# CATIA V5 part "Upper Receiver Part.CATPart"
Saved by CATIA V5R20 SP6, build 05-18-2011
Part number: Upper Receiver Part
Bounding box of the stored display mesh (mm): x -116 to 116, y -29.997 to 29.997, z -32.891 to 0
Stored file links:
  E:\LCS\20170920\#01 CATIA Lecture Materials\#55 GSD18\#01 CATPart\Upper Receiver Part.CATPart
  E:\LCS\20170920\#01 CATIA Lecture Materials\#55 GSD18\#01 CATPart\Receiver Assembly.CATProduct
  E:\LCS\20170920\#01 CATIA Lecture Materials\#55 GSD18\#01 CATPart\Skeleton.CATPart
  E:\LCS\20170920\#01 CATIA Lecture Materials\#55 GSD18\#01 CATPart\Lower Receiver Part.CATPart
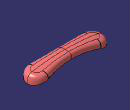
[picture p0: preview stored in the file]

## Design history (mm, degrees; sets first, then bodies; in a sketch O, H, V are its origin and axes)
Set1
  DatumCurve1 "Upper Boundary Curve": linked copy from another document
  DatumCurve2 "Middle Boundary Curve": linked copy from another document
  DatumCurve3 "Upper Guide Curve": linked copy from another document
  DatumCurve4 "Lower Guide Curve": linked copy from another document
Set2 "Surface Data"
  Set3 "Cavity Body"
    CurvePar1 "Center Curve": Offset DatumCurve1, Offset2 0, Offset1 100
    Sweep1 "Top Surface": type Circle, Guide CurvePar1, Reference DatumCurve1, Radius 20, Angle1 0, Angle2 45
    Sweep2 "Parting Surface": type Segment, GuideCrv DatumCurve2, Length1 80, Length2 0, Angle 0, DraftDirection zx-plane
    Project1 "Side Surface Guide Curve 01": ToProject DatumCurve3, Support Sweep1, Direction xy-plane
    Sweep3 "Side Surface": type Conic, Guide ({sweepconicextendedguide Guide Project1, Reference Sweep1, Angle 0}; {sweepconicextendedguide Guide DatumCurve4, Reference xy-plane, Angle 92}), Parameter 0.6
    Split1: ToCut Sweep1, Cutting Project1
    Join1: Elements (Split1; Sweep3)
    Split2: ToCut Join1, Cutting yz-plane
    Symmetry1: Reference zx-plane, ToTransfor Split2
    Join2: Elements (Split2; Symmetry1)
    Symmetry2: Reference yz-plane, ToTransfor Join2
  Join3 "Cavity Final Surface": Elements (Symmetry2; Join2)
  Set4 "Core Body"
    Offset1: Offset Sweep2, Length -2
    Offset2: Offset Join1, Length -1
    Offset3: Offset Join1, Length -2
    Trim1: Trimmed (Sweep2; Offset2; Offset1; Offset3)
    Split3: ToCut Trim1, Cutting yz-plane
    Symmetry3: Reference zx-plane, ToTransfor Split3
    Join4: Elements (Split3; Symmetry3)
    Symmetry4: Reference yz-plane, ToTransfor Join4
  Join5 "Core Final Surface": Elements (Join4; Symmetry4)
  Trim2 "Upper Final Surface": Trimmed (Join3; Join5)
Body1 (main body)
Body2 "Upper Part"
  CloseSurface1: CloseElement Trim2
